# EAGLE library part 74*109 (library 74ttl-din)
Dual J-K positive edge triggered FLIP FLOP, preset and clear
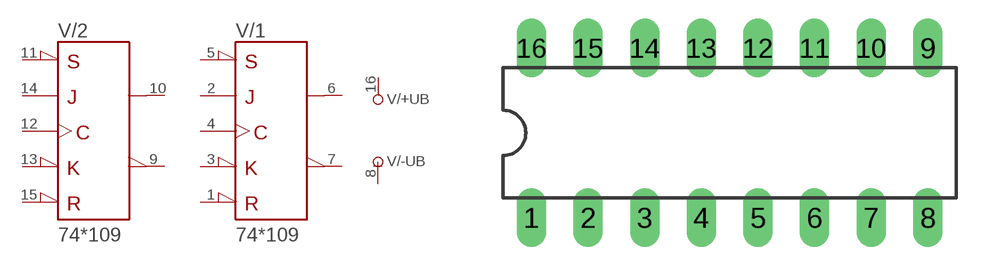
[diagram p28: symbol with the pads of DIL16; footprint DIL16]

Designator prefix V; gates /+UB=+UB /-UB=-UB /1=109 /2=109

## 74109N  [DIL16]
1  /1:CLR\  in
2  /1:J  in
3  /1:K\  in
4  /1:CLK  in
5  /1:PRE\  in
6  /1:Q  out
7  /1:Q\  out
8  /-UB:-UB  pwr
9  /2:Q\  out
10  /2:Q  out
11  /2:PRE\  in
12  /2:CLK  in
13  /2:K\  in
14  /2:J  in
15  /2:CLR\  in
16  /+UB:+UB  pwr

## Footprint DIL16 (pad centres in mm)
Dual In Line Package
drill 0.813 long: 1 -8.89,-3.81; 2 -6.35,-3.81; 3 -3.81,-3.81; 4 -1.27,-3.81; 5 1.27,-3.81; 6 3.81,-3.81; 7 6.35,-3.81; 8 8.89,-3.81; 9 8.89,3.81; 10 6.35,3.81; 11 3.81,3.81; 12 1.27,3.81; 13 -1.27,3.81; 14 -3.81,3.81; 15 -6.35,3.81; 16 -8.89,3.81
